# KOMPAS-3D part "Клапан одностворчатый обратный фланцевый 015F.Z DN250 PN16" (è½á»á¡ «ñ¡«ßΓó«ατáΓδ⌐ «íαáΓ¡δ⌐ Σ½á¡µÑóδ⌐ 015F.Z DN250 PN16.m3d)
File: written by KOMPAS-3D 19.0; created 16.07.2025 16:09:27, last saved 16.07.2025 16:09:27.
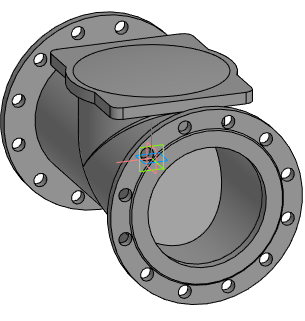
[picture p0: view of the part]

Document properties: Полное имя файла: E:\Dendor Работа Сачек\3D для проектировщиков\5.4 Тип 015F.Z. Клапан одностворчатый обратный фланцевый\stp_Клапан одностворчатый обратный фланцевый 015F.Z PN10_16\Клапан одностворчатый обратный фланцевый 015F.Z DN250 PN16.m3d

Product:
- Part/product: Клапан одностворчатый обратный фланцевый 015F.Z DN250 PN16

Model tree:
1. Операция без истории:1  (labels: Клапан одностворчатый обратный фланцевый 015F.Z DN250 PN16)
